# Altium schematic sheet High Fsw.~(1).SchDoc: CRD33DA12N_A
size 431 x 279 mm; Date: 09.11.2024; Revision: 2; SheetNumber: 1; SheetTotal: 3; SheetSize: B
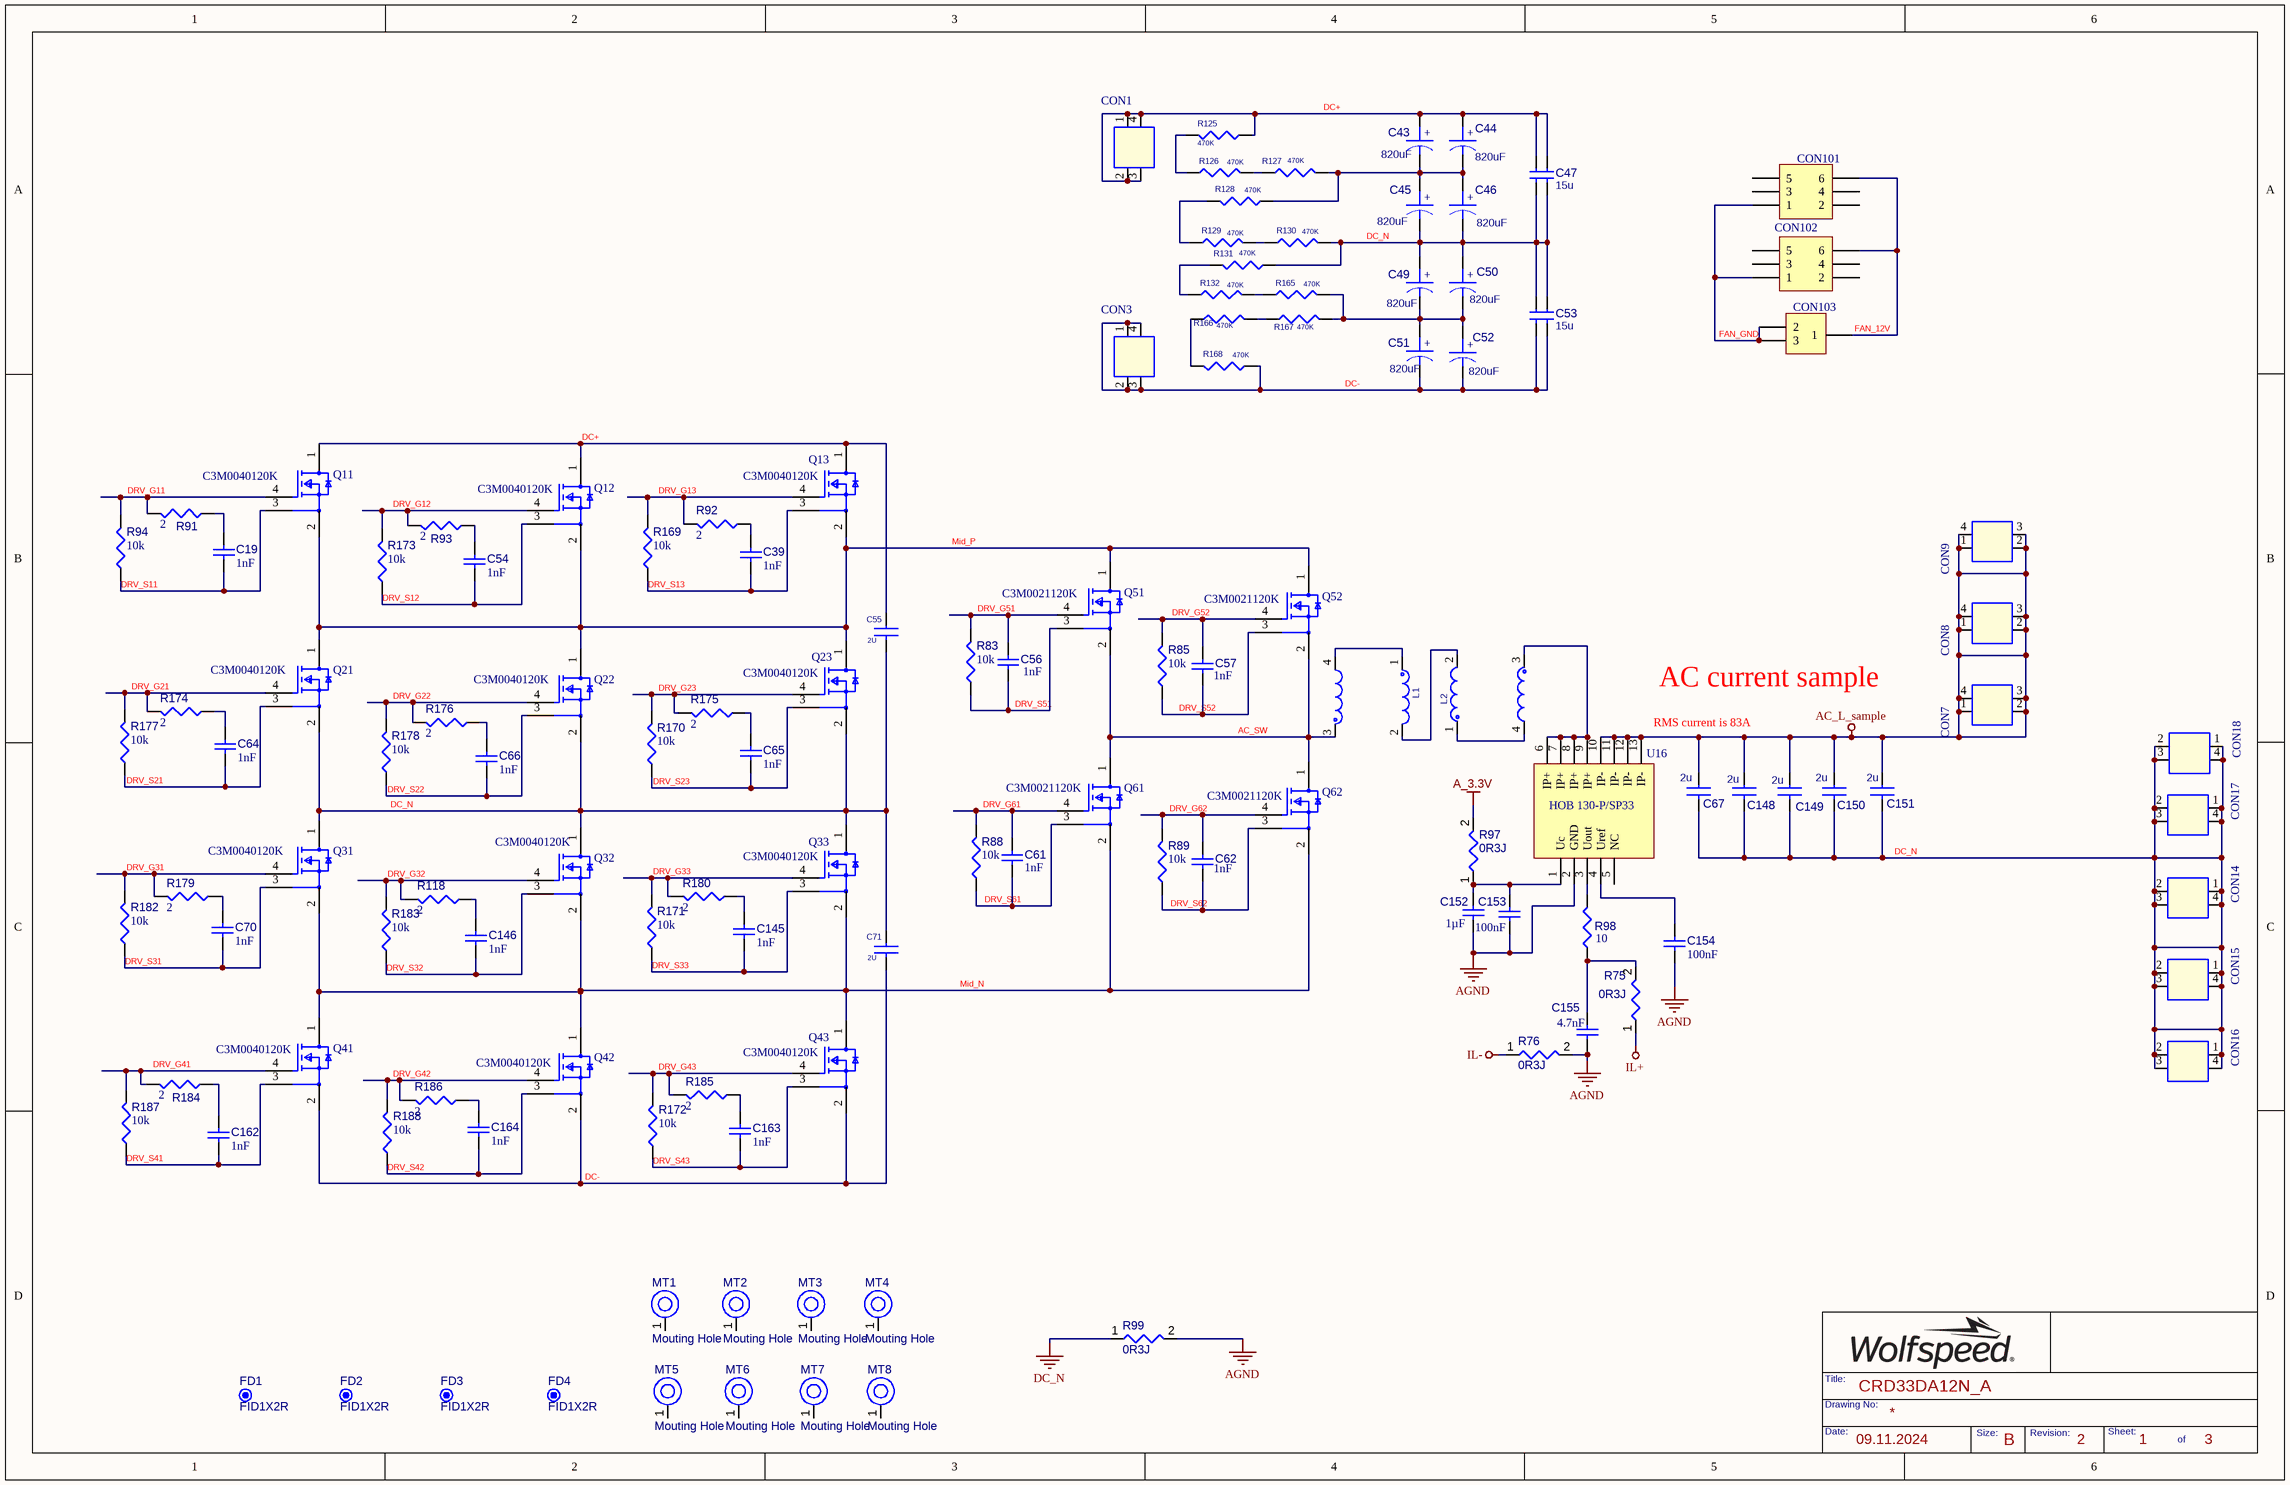
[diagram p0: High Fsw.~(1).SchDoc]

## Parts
C19  value 1nF  [FP-C0603C-CF-IPC_B]  (hidden comment: C0603C104K5RAC7411)
C39  value 1nF  [FP-C0603C-CF-IPC_B]  (hidden comment: C0603C104K5RAC7411)
C43  820uF  [CAP2_2100_6000_3000]
C44  820uF  [CAP2_2100_6000_3000]
C45  820uF  [CAP2_2100_6000_3000]
C46  820uF  [CAP2_2100_6000_3000]
C47  15u  [capfilm_42x20mm]
C49  820uF  [CAP2_2100_6000_3000]
C50  820uF  [CAP2_2100_6000_3000]
C51  820uF  [CAP2_2100_6000_3000]
C52  820uF  [CAP2_2100_6000_3000]
C53  15u  [capfilm_42x20mm]
C54  value 1nF  [FP-C0603C-CF-IPC_B]  (hidden comment: C0603C104K5RAC7411)
C55  2U  [capfilm_31_5x12_5mm]
C56  value 1nF  [FP-C0603C-CF-IPC_B]  (hidden comment: C0603C104K5RAC7411)
C57  value 1nF  [FP-C0603C-CF-IPC_B]  (hidden comment: C0603C104K5RAC7411)
C61  value 1nF  [FP-C0603C-CF-IPC_B]  (hidden comment: C0603C104K5RAC7411)
C62  value 1nF  [FP-C0603C-CF-IPC_B]  (hidden comment: C0603C104K5RAC7411)
C64  value 1nF  [FP-C0603C-CF-IPC_B]  (hidden comment: C0603C104K5RAC7411)
C65  value 1nF  [FP-C0603C-CF-IPC_B]  (hidden comment: C0603C104K5RAC7411)
C66  value 1nF  [FP-C0603C-CF-IPC_B]  (hidden comment: C0603C104K5RAC7411)
C67  2u  [CAP2_3750-4200X3000X4500]
C70  value 1nF  [FP-C0603C-CF-IPC_B]  (hidden comment: C0603C104K5RAC7411)
C71  2U  [capfilm_31_5x12_5mm]
C145  value 1nF  [FP-C0603C-CF-IPC_B]  (hidden comment: C0603C104K5RAC7411)
C146  value 1nF  [FP-C0603C-CF-IPC_B]  (hidden comment: C0603C104K5RAC7411)
C148  2u  [CAP2_3750-4200X3000X4500]
C149  2u  [CAP2_3750-4200X3000X4500]
C150  2u  [CAP2_3750-4200X3000X4500]
C151  2u  [CAP2_3750-4200X3000X4500]
C152  value 1µF  [FP-CL21-IPC_A]  (hidden comment: CL21B105KBFNNNG)
C153  value 100nF  [FP-C0603C-CF-IPC_B]  (hidden comment: C0603C104K5RAC7411)
C154  value 100nF  [FP-C0603C-CF-IPC_B]  (hidden comment: C0603C104K5RAC7411)
C155  value 4.7nF  [FP-C0603C-CF-IPC_B]  (hidden comment: C0603C472K5RACAUTO)
C162  value 1nF  [FP-C0603C-CF-IPC_B]  (hidden comment: C0603C104K5RAC7411)
C163  value 1nF  [FP-C0603C-CF-IPC_B]  (hidden comment: C0603C104K5RAC7411)
C164  value 1nF  [FP-C0603C-CF-IPC_B]  (hidden comment: C0603C104K5RAC7411)
CON1  Connecter  [thread4_9p9x5_1110x920]  (value not drawn)
CON3  Connecter  [thread4_9p9x5_1110x920]  (value not drawn)
CON7  Connecter  [thread4_9p9x5_1110x920]  (value not drawn)
CON8  Connecter  [thread4_9p9x5_1110x920]  (value not drawn)
CON9  Connecter  [thread4_9p9x5_1110x920]  (value not drawn)
CON14  Connecter  [thread4_9p9x5_1110x920]  (value not drawn)
CON15  Connecter  [thread4_9p9x5_1110x920]  (value not drawn)
CON16  Connecter  [thread4_9p9x5_1110x920]  (value not drawn)
CON17  Connecter  [thread4_9p9x5_1110x920]  (value not drawn)
CON18  Connecter  [thread4_9p9x5_1110x920]  (value not drawn)
CON101  CON_3*2  [MOLEX_5557_6PIN]  (value not drawn)
CON102  CON_3*2  [MOLEX_5557_6PIN]  (value not drawn)
CON103  CON_3_1  [DC-005]  (value not drawn)
FD1  FID1X2R  [FID1X2R]  (no BOM)
FD2  FID1X2R  [FID1X2R]  (no BOM)
FD3  FID1X2R  [FID1X2R]  (no BOM)
FD4  FID1X2R  [FID1X2R]  (no BOM)
L1  70uH Inv inductor  [L_116x64x60]  (value not drawn)
L2  70uH Inv inductor  [L_116x64x60]  (value not drawn)
MT1  Mouting Hole  [MTG330N]  (no BOM)
MT2  Mouting Hole  [MTG330N]  (no BOM)
MT3  Mouting Hole  [MTG330N]  (no BOM)
MT4  Mouting Hole  [MTG330N]  (no BOM)
MT5  Mouting Hole  [MTG330N]  (no BOM)
MT6  Mouting Hole  [MTG330N]  (no BOM)
MT7  Mouting Hole  [MTG330N]  (no BOM)
MT8  Mouting Hole  [MTG330N]  (no BOM)
Q11  C3M0040120K  [TO-247-4_CRW]
Q12  C3M0040120K  [TO-247-4_CRW]
Q13  C3M0040120K  [TO-247-4_CRW]
Q21  C3M0040120K  [TO-247-4_CRW]
Q22  C3M0040120K  [TO-247-4_CRW]
Q23  C3M0040120K  [TO-247-4_CRW]
Q31  C3M0040120K  [TO-247-4_CRW]
Q32  C3M0040120K  [TO-247-4_CRW]
Q33  C3M0040120K  [TO-247-4_CRW]
Q41  C3M0040120K  [TO-247-4_CRW]
Q42  C3M0040120K  [TO-247-4_CRW]
Q43  C3M0040120K  [TO-247-4_CRW]
Q51  C3M0021120K  [TO-247-4_CRW]
Q52  C3M0021120K  [TO-247-4_CRW]
Q61  C3M0021120K  [TO-247-4_CRW]
Q62  C3M0021120K  [TO-247-4_CRW]
R75  0R3J  [RESC0603(1608)_L]
R76  0R3J  [RESC0603(1608)_L]
R83  value 10k  [FP-AC0603-IPC_B]  (hidden comment: ERJ-3EKF1002V)
R85  value 10k  [FP-AC0603-IPC_B]  (hidden comment: ERJ-3EKF1002V)
R88  value 10k  [FP-AC0603-IPC_B]  (hidden comment: ERJ-3EKF1002V)
R89  value 10k  [FP-AC0603-IPC_B]  (hidden comment: ERJ-3EKF1002V)
R91  value 2  [FP-AC0603-IPC_B]  (hidden comment: RC0603FR-072RL)
R92  value 2  [FP-AC0603-IPC_B]  (hidden comment: RC0603FR-072RL)
R93  value 2  [FP-AC0603-IPC_B]  (hidden comment: RC0603FR-072RL)
R94  value 10k  [FP-AC0603-IPC_B]  (hidden comment: ERJ-3EKF1002V)
R97  0R3J  [RESC0603(1608)_L]
R98  value 10  [RESC3015X06N]  (hidden comment: RMCF1206FT10R0)
R99  0R3J  [RESC0603(1608)_L]
R118  value 2  [FP-AC0603-IPC_B]  (hidden comment: RC0603FR-072RL)
R125  470K  [1206]
R126  470K  [1206]
R127  470K  [1206]
R128  470K  [1206]
R129  470K  [1206]
R130  470K  [1206]
R131  470K  [1206]
R132  470K  [1206]
R165  470K  [1206]
R166  470K  [1206]
R167  470K  [1206]
R168  470K  [1206]
R169  value 10k  [FP-AC0603-IPC_B]  (hidden comment: ERJ-3EKF1002V)
R170  value 10k  [FP-AC0603-IPC_B]  (hidden comment: ERJ-3EKF1002V)
R171  value 10k  [FP-AC0603-IPC_B]  (hidden comment: ERJ-3EKF1002V)
R172  value 10k  [FP-AC0603-IPC_B]  (hidden comment: ERJ-3EKF1002V)
R173  value 10k  [FP-AC0603-IPC_B]  (hidden comment: ERJ-3EKF1002V)
R174  value 2  [FP-AC0603-IPC_B]  (hidden comment: RC0603FR-072RL)
R175  value 2  [FP-AC0603-IPC_B]  (hidden comment: RC0603FR-072RL)
R176  value 2  [FP-AC0603-IPC_B]  (hidden comment: RC0603FR-072RL)
R177  value 10k  [FP-AC0603-IPC_B]  (hidden comment: ERJ-3EKF1002V)
R178  value 10k  [FP-AC0603-IPC_B]  (hidden comment: ERJ-3EKF1002V)
R179  value 2  [FP-AC0603-IPC_B]  (hidden comment: RC0603FR-072RL)
R180  value 2  [FP-AC0603-IPC_B]  (hidden comment: RC0603FR-072RL)
R182  value 10k  [FP-AC0603-IPC_B]  (hidden comment: ERJ-3EKF1002V)
R183  value 10k  [FP-AC0603-IPC_B]  (hidden comment: ERJ-3EKF1002V)
R184  value 2  [FP-AC0603-IPC_B]  (hidden comment: RC0603FR-072RL)
R185  value 2  [FP-AC0603-IPC_B]  (hidden comment: RC0603FR-072RL)
R186  value 2  [FP-AC0603-IPC_B]  (hidden comment: RC0603FR-072RL)
R187  value 10k  [FP-AC0603-IPC_B]  (hidden comment: ERJ-3EKF1002V)
R188  value 10k  [FP-AC0603-IPC_B]  (hidden comment: ERJ-3EKF1002V)
U16  HOB 130-P/SP33  [CT13_HOB-P_SP33]

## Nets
A_3.3V: R97.2
AC_L_sample: C67.1 C148.1 C149.1 C150.1 C151.1 CON7.1 CON7.2 CON7.3 CON7.4 CON8.1 CON8.2 CON8.3 CON8.4 CON9.1 CON9.2 CON9.3 CON9.4 U16.10(IP-) U16.11(IP-) U16.12(IP-) U16.13(IP-)
AGND: C152.2 C153.2 C154.2 C155.2 R76.2 R99.2 U16.2(GND)
DC_N: C45.2 C46.2 C47.2 C47.4 C49.1 C50.1 C53.1 C53.3 C55.2 C67.2 C71.1 C148.2 C149.2 C150.2 C151.2 CON14.1 CON14.2 CON14.3 CON14.4 CON15.1 CON15.2 CON15.3 CON15.4 CON16.1 CON16.2 CON16.3 CON16.4 CON17.1 CON17.2 CON17.3 CON17.4 CON18.1 CON18.2 CON18.3 CON18.4 Q21.2(Power_Source) Q22.2(Power_Source) Q23.2(Power_Source) Q31.1(Drain) Q32.1(Drain) Q33.1(Drain) R99.1 R130.2 R131.1
IL+: R75.1
IL-: R76.1
AC_SW: L1.3 Q51.2(Power_Source) Q52.2(Power_Source) Q61.1(Drain) Q62.1(Drain)
DC+: C43.1 C44.1 C47.1 C47.3 C55.1 CON1.1 CON1.2 CON1.3 CON1.4 Q11.1(Drain) Q12.1(Drain) Q13.1(Drain) R125.1
DC-: C51.2 C52.2 C53.2 C53.4 C71.2 CON3.1 CON3.2 CON3.3 CON3.4 Q41.2(Power_Source) Q42.2(Power_Source) Q43.2(Power_Source) R168.1
DRV_G11: Q11.4(Gate) R91.2 R94.2
DRV_G12: Q12.4(Gate) R93.2 R173.2
DRV_G13: Q13.4(Gate) R92.2 R169.2
DRV_G21: Q21.4(Gate) R174.2 R177.2
DRV_G22: Q22.4(Gate) R176.2 R178.2
DRV_G23: Q23.4(Gate) R170.2 R175.2
DRV_G31: Q31.4(Gate) R179.2 R182.2
DRV_G32: Q32.4(Gate) R118.2 R183.2
DRV_G33: Q33.4(Gate) R171.2 R180.2
DRV_G41: Q41.4(Gate) R184.2 R187.2
DRV_G42: Q42.4(Gate) R186.2 R188.2
DRV_G43: Q43.4(Gate) R172.2 R185.2
DRV_G51: C56.2 Q51.4(Gate) R83.2
DRV_G52: C57.2 Q52.4(Gate) R85.2
DRV_G61: C61.2 Q61.4(Gate) R88.2
DRV_G62: C62.2 Q62.4(Gate) R89.2
DRV_S11: C19.1 Q11.3(Driver_Source) R94.1
DRV_S12: C54.1 Q12.3(Driver_Source) R173.1
DRV_S13: C39.1 Q13.3(Driver_Source) R169.1
DRV_S21: C64.1 Q21.3(Driver_Source) R177.1
DRV_S22: C66.1 Q22.3(Driver_Source) R178.1
DRV_S23: C65.1 Q23.3(Driver_Source) R170.1
DRV_S31: C70.1 Q31.3(Driver_Source) R182.1
DRV_S32: C146.1 Q32.3(Driver_Source) R183.1
DRV_S33: C145.1 Q33.3(Driver_Source) R171.1
DRV_S41: C162.1 Q41.3(Driver_Source) R187.1
DRV_S42: C164.1 Q42.3(Driver_Source) R188.1
DRV_S43: C163.2 Q43.3(Driver_Source) R172.1
DRV_S51: C56.1 Q51.3(Driver_Source) R83.1
DRV_S52: C57.1 Q52.3(Driver_Source) R85.1
DRV_S61: C61.1 Q61.3(Driver_Source) R88.1
DRV_S62: C62.1 Q62.3(Driver_Source) R89.1
FAN_12V: CON101.6 CON102.6 CON103.1
FAN_GND: CON101.1 CON102.1 CON103.2 CON103.3
Mid_N: Q31.2(Power_Source) Q32.2(Power_Source) Q33.2(Power_Source) Q41.1(Drain) Q42.1(Drain) Q43.1(Drain) Q61.2(Power_Source) Q62.2(Power_Source)
Mid_P: Q11.2(Power_Source) Q12.2(Power_Source) Q13.2(Power_Source) Q21.1(Drain) Q22.1(Drain) Q23.1(Drain) Q51.1(Drain) Q52.1(Drain)
NetC19_2: C19.2 R91.1
NetC39_2: C39.2 R92.1
NetC43_2: C43.2 C44.2 C45.1 C46.1 R127.2 R128.1
NetC49_2: C49.2 C50.2 C51.1 C52.1 R165.2 R167.2
NetC54_2: C54.2 R93.1
NetC64_2: C64.2 R174.1
NetC65_2: C65.2 R175.1
NetC66_2: C66.2 R176.1
NetC70_2: C70.2 R179.1
NetC145_2: C145.2 R180.1
NetC146_2: C146.2 R118.1
NetC152_1: C152.1 C153.1 R97.1 U16.1(Uc)
NetC154_1: C154.1 U16.4(Uref)
NetC155_1: C155.1 R75.2 R98.1
NetC162_2: C162.2 R184.1
NetC163_1: C163.1 R185.1
NetC164_2: C164.2 R186.1
NetL1_1: L1.1 L1.4
NetL1_2: L1.2 L2.2
NetL2_1: L2.1 L2.4
NetL2_3: L2.3 U16.6(IP+) U16.7(IP+) U16.8(IP+) U16.9(IP+)
NetR98_2: R98.2 U16.3(Uout)
NetR125_2: R125.2 R126.1
NetR126_2: R126.2 R127.1
NetR128_2: R128.2 R129.1
NetR129_2: R129.2 R130.1
NetR131_2: R131.2 R132.1
NetR132_2: R132.2 R165.1
NetR166_1: R166.1 R168.2
NetR166_2: R166.2 R167.1

Not connected (* = marked no-connect by the designer): CON101 2 3 4 5; CON102 2 3 4 5; MT1 1(H1); MT2 1(H1); MT3 1(H1); MT4 1(H1); MT5 1(H1); MT6 1(H1); MT7 1(H1); MT8 1(H1); U16 5(NC)

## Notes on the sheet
- AC current sample
- RMS current is 83A

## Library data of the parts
C19 C39 C54 C56 C57 C61 C62 C64-C66 C70 C145 C146 C162-C164 = CMP-001-00086-7: Ceramic Capacitor, Multilayer, Ceramic, 50V, 10% +Tol, 10% -Tol, X7R, 15% TC, 0.1uF, Surface Mount, 0603
C43-C46 C49-C52 = 820u: CAP ALUM 820UF 20% 450V RADIAL; PCB Footprint: C0805
C47 C53 = B32776G9156K000: 15UF, 900V; PCB Footprint: C0805
C55 C71 = CAP NP_Dup1: CAP FILM 2UF 10% 1.1KVDC RADIAL; Manufacturer: EPCOS; PCB Footprint: C0603; PN: B32774D0205K000
C67 C148-C151 = B32656A0225K000: 2uF 500VAC; PCB Footprint: C0805
C152 = CMP-001-00150-2: Cap Ceramic 1uF 50V X7R 10% SMD 0805 125°C Embossed Plastic T/R; MFG: Samsung Electromechanics
C153 C154 = CMP-001-00086-11: Ceramic Capacitor, Multilayer, Ceramic, 50V, 10% +Tol, 10% -Tol, X7R, 15% TC, 0.1uF, Surface Mount, 0603
C155 = CMP-001-00119-9: Ceramic Capacitor, Multilayer, Ceramic, 50V, 10% +Tol, 10% -Tol, X7R, 15% TC, 0.0047uF, Surface Mount, 0603
FD1-FD4 = CMP-00028-00005-1: Fiducial - Round 1x2mm
L1 L2 = 70uH: 70uH at 85A, 52uH at 120A; PCB Footprint: ecap_d8p3_5
MT1-MT8 = MTG330N: PCB Mounting Hole
Q11-Q13 Q21-Q23 Q31-Q33 Q41-Q43 = C3M0040120K: SiC MOSFET, 1200V 40mohm, TO247-4
Q51 Q52 Q61 Q62 = C3M0021120K: Silicon Carbide Power MOSFET C3M Planar MOSFET Technology N-Channel Enhancement Mode; Vgs (Max): 19V; Transistor Type: N-Channel MOSFET; Power: 405W
R75 R76 R97 R99 = CMP-009-00063-1: Jumper 0603 (1608 Metric); Value: 0Ω
R83 R85 R88 R89 R94 R169-R173 R177 R178 R182 R183 R187 R188 = CMP-009-00014-4: Fixed Resistor, Metal Glaze/thick Film, 0.1W, 10000ohm, 75V, 1% +/-Tol, 100ppm/Cel, Surface Mount, 0603; Power: 100mW
R91-R93 R118 R174-R176 R179 R180 R184-R186 = CMP-009-00038-6: Fixed Resistor, Metal Glaze/thick Film, 0.1W, 2ohm, 75V, 1% +/-Tol, 100ppm/Cel, Surface Mount, 0603; Power: 100mW
R98 = CMP-009-00067-6: Fixed Resistor, Metal Glaze/thick Film, 0.25W, 10ohm, 200V, 1% +/-Tol, 100ppm/Cel, Surface Mount, 1206; Power: 250mW
R125-R132 R165-R168 = RESISTOR_Dup1: RES SMD 470K OHM 1% 1/10W 1206; Manufacturer: Yageo; PCB Footprint: R1206; PN: AC1206FR-07470KL
U16 = HOB 130-P/SP33: Current Transducer, ±250A, 1MHz, 3.3V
